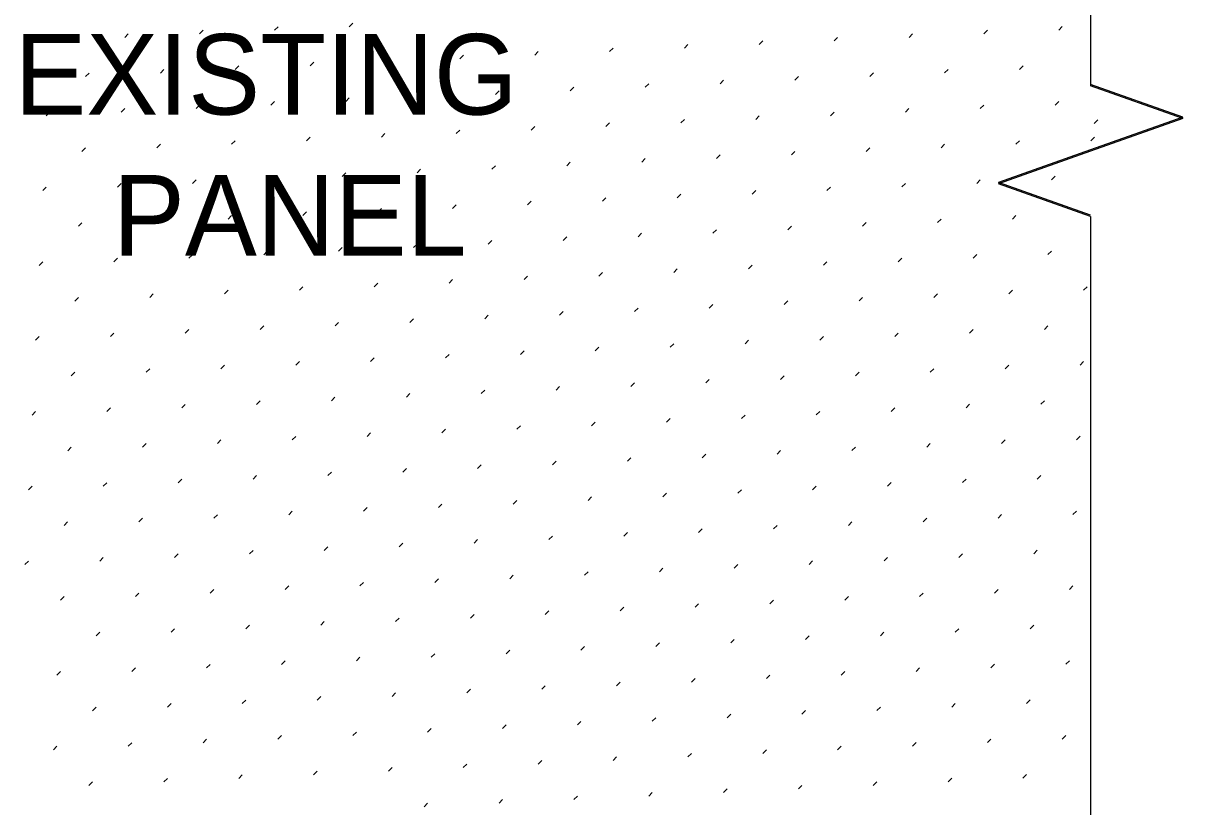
# Model space of a CAD drawing. Extents: x 49991.4 to 50021, y 49987.6 to 50011.4.
# Drawn here: x 50014.071 to 50015.222, y 49994.884 to 49995.662 of the extents above; entities that cross this region are included whole.
import ezdxf

# ---------------------------------------------------------------- set-up
doc = ezdxf.new("R2010")
doc.units = 0
for name, color, linetype in [('Level 10', 7, 'Continuous'), ('Level 2', 7, 'Continuous'), ('Level 6', 7, 'Continuous')]:
    doc.layers.add(name, color=color, linetype=linetype)

msp = doc.modelspace()

# ---------------------------------------------------------------- linework, layer by layer
at = {"layer": 'Level 10'}
for p, q in [((50014.3948, 49995.6587), (50014.3984, 49995.6623)), ((50014.1721, 49995.6481), (50014.1756, 49995.6516)), ((50014.2463, 49995.6516), (50014.2499, 49995.6552)), ((50014.3206, 49995.6552), (50014.3241, 49995.6587)), ((50014.95, 49995.6482), (50014.9535, 49995.6517)), ((50015.0242, 49995.6517), (50015.0277, 49995.6552)), ((50015.0985, 49995.6552), (50015.102, 49995.6588)), ((50014.0978, 49995.6445), (50014.1013, 49995.6481)), ((50014.7272, 49995.6375), (50014.7307, 49995.6411)), ((50014.8014, 49995.6411), (50014.805, 49995.6446)), ((50014.8757, 49995.6446), (50014.8792, 49995.6482)), ((50014.5044, 49995.6269), (50014.508, 49995.6304)), ((50014.5787, 49995.6304), (50014.5822, 49995.634)), ((50014.6529, 49995.634), (50014.6565, 49995.6375)), ((50014.2074, 49995.6127), (50014.211, 49995.6163)), ((50014.2817, 49995.6163), (50014.2852, 49995.6198)), ((50014.3559, 49995.6198), (50014.3595, 49995.6234)), ((50014.4302, 49995.6234), (50014.4337, 49995.6269)), ((50014.9853, 49995.6128), (50014.9888, 49995.6163)), ((50015.0596, 49995.6163), (50015.0631, 49995.6199)), ((50014.1332, 49995.6092), (50014.1367, 49995.6127)), ((50014.7625, 49995.6022), (50014.7661, 49995.6057)), ((50014.8368, 49995.6057), (50014.8403, 49995.6093)), ((50014.9111, 49995.6093), (50014.9146, 49995.6128)), ((50014.5398, 49995.5916), (50014.5433, 49995.5951)), ((50014.614, 49995.5951), (50014.6176, 49995.5986)), ((50014.6883, 49995.5986), (50014.6918, 49995.6022)), ((50014.317, 49995.5809), (50014.3206, 49995.5845)), ((50014.3913, 49995.5845), (50014.3948, 49995.588)), ((50014.4655, 49995.588), (50014.4691, 49995.5915)), ((50015.0949, 49995.581), (50015.0985, 49995.5845)), ((50014.0943, 49995.5703), (50014.0978, 49995.5738)), ((50014.1685, 49995.5738), (50014.1721, 49995.5774)), ((50014.2428, 49995.5774), (50014.2463, 49995.5809)), ((50014.7979, 49995.5668), (50014.8014, 49995.5704)), ((50014.8722, 49995.5704), (50014.8757, 49995.5739)), ((50014.9464, 49995.5739), (50014.9499, 49995.5774)), ((50015.0207, 49995.5775), (50015.0242, 49995.581)), ((50014.5751, 49995.5562), (50014.5787, 49995.5597)), ((50014.6494, 49995.5597), (50014.6529, 49995.5633)), ((50014.7236, 49995.5633), (50014.7272, 49995.5668)), ((50015.1337, 49995.5628), (50015.1372, 49995.5664)), ((50014.3524, 49995.5456), (50014.3559, 49995.5491)), ((50014.4266, 49995.5491), (50014.4302, 49995.5526)), ((50014.5009, 49995.5527), (50014.5044, 49995.5562)), ((50015.1303, 49995.5456), (50015.1338, 49995.5492)), ((50014.1296, 49995.5349), (50014.1332, 49995.5385)), ((50014.2039, 49995.5385), (50014.2074, 49995.542)), ((50014.2781, 49995.542), (50014.2817, 49995.5456)), ((50014.9075, 49995.535), (50014.911, 49995.5385)), ((50014.9818, 49995.5386), (50014.9853, 49995.5421)), ((50015.056, 49995.5421), (50015.0596, 49995.5456)), ((50014.6105, 49995.5208), (50014.614, 49995.5244)), ((50014.6848, 49995.5244), (50014.6883, 49995.5279)), ((50014.759, 49995.5279), (50014.7625, 49995.5315)), ((50014.8333, 49995.5315), (50014.8368, 49995.535)), ((50014.3877, 49995.5102), (50014.3913, 49995.5137)), ((50014.462, 49995.5138), (50014.4655, 49995.5173)), ((50014.5362, 49995.5173), (50014.5398, 49995.5208)), ((50014.165, 49995.4996), (50014.1685, 49995.5031)), ((50014.2392, 49995.5031), (50014.2428, 49995.5067)), ((50014.3135, 49995.5067), (50014.317, 49995.5102)), ((50014.9429, 49995.4997), (50014.9464, 49995.5032)), ((50015.0171, 49995.5032), (50015.0207, 49995.5067)), ((50015.0914, 49995.5067), (50015.0949, 49995.5103)), ((50014.0907, 49995.496), (50014.0943, 49995.4996)), ((50014.7201, 49995.489), (50014.7236, 49995.4926)), ((50014.7944, 49995.4926), (50014.7979, 49995.4961)), ((50014.8686, 49995.4961), (50014.8721, 49995.4996)), ((50014.4231, 49995.4749), (50014.4266, 49995.4784)), ((50014.4973, 49995.4784), (50014.5009, 49995.4819)), ((50014.5716, 49995.4819), (50014.5751, 49995.4855)), ((50014.6459, 49995.4855), (50014.6494, 49995.489)), ((50014.2003, 49995.4642), (50014.2039, 49995.4678)), ((50014.2746, 49995.4678), (50014.2781, 49995.4713)), ((50014.3488, 49995.4713), (50014.3524, 49995.4749)), ((50014.9782, 49995.4643), (50014.9818, 49995.4678)), ((50015.0525, 49995.4678), (50015.056, 49995.4714)), ((50014.1261, 49995.4607), (50014.1296, 49995.4642)), ((50014.7555, 49995.4537), (50014.759, 49995.4572)), ((50014.8297, 49995.4572), (50014.8333, 49995.4608)), ((50014.904, 49995.4608), (50014.9075, 49995.4643)), ((50014.5327, 49995.443), (50014.5362, 49995.4466)), ((50014.607, 49995.4466), (50014.6105, 49995.4501)), ((50014.6812, 49995.4501), (50014.6847, 49995.4537)), ((50014.2357, 49995.4289), (50014.2392, 49995.4324)), ((50014.3099, 49995.4324), (50014.3135, 49995.436)), ((50014.3842, 49995.436), (50014.3877, 49995.4395)), ((50014.4584, 49995.4395), (50014.462, 49995.443)), ((50015.0136, 49995.4289), (50015.0171, 49995.4325)), ((50015.0878, 49995.4325), (50015.0914, 49995.436)), ((50014.0872, 49995.4218), (50014.0907, 49995.4253)), ((50014.1614, 49995.4253), (50014.165, 49995.4289)), ((50014.7908, 49995.4183), (50014.7944, 49995.4219)), ((50014.8651, 49995.4219), (50014.8686, 49995.4254)), ((50014.9393, 49995.4254), (50014.9429, 49995.4289)), ((50014.5681, 49995.4077), (50014.5716, 49995.4112)), ((50014.6423, 49995.4112), (50014.6458, 49995.4148)), ((50014.7166, 49995.4148), (50014.7201, 49995.4183)), ((50014.3453, 49995.3971), (50014.3488, 49995.4006)), ((50014.4196, 49995.4006), (50014.4231, 49995.4041)), ((50014.4938, 49995.4041), (50014.4973, 49995.4077)), ((50015.1232, 49995.3971), (50015.1267, 49995.4007)), ((50014.1225, 49995.3864), (50014.1261, 49995.39)), ((50014.1968, 49995.39), (50014.2003, 49995.3935)), ((50014.271, 49995.3935), (50014.2746, 49995.3971)), ((50014.8262, 49995.383), (50014.8297, 49995.3865)), ((50014.9004, 49995.3865), (50014.904, 49995.39)), ((50014.9747, 49995.39), (50014.9782, 49995.3936)), ((50015.0489, 49995.3936), (50015.0525, 49995.3971)), ((50014.6034, 49995.3723), (50014.6069, 49995.3759)), ((50014.6777, 49995.3759), (50014.6812, 49995.3794)), ((50014.7519, 49995.3794), (50014.7555, 49995.383)), ((50014.3807, 49995.3617), (50014.3842, 49995.3652)), ((50014.4549, 49995.3652), (50014.4584, 49995.3688)), ((50014.5292, 49995.3688), (50014.5327, 49995.3723)), ((50014.1579, 49995.3511), (50014.1614, 49995.3546)), ((50014.2321, 49995.3546), (50014.2357, 49995.3582)), ((50014.3064, 49995.3582), (50014.3099, 49995.3617)), ((50014.9358, 49995.3511), (50014.9393, 49995.3547)), ((50015.01, 49995.3547), (50015.0136, 49995.3582)), ((50015.0843, 49995.3582), (50015.0878, 49995.3618)), ((50014.0836, 49995.3475), (50014.0872, 49995.3511)), ((50014.6388, 49995.337), (50014.6423, 49995.3405)), ((50014.713, 49995.3405), (50014.7166, 49995.3441)), ((50014.7873, 49995.3441), (50014.7908, 49995.3476)), ((50014.8615, 49995.3476), (50014.8651, 49995.3511)), ((50014.416, 49995.3264), (50014.4195, 49995.3299)), ((50014.4903, 49995.3299), (50014.4938, 49995.3334)), ((50014.5645, 49995.3334), (50014.5681, 49995.337)), ((50014.1932, 49995.3157), (50014.1968, 49995.3193)), ((50014.2675, 49995.3193), (50014.271, 49995.3228)), ((50014.3418, 49995.3228), (50014.3453, 49995.3263)), ((50014.9711, 49995.3158), (50014.9747, 49995.3193)), ((50015.0454, 49995.3193), (50015.0489, 49995.3229)), ((50015.1196, 49995.3229), (50015.1232, 49995.3264)), ((50014.119, 49995.3122), (50014.1225, 49995.3157)), ((50014.7484, 49995.3052), (50014.7519, 49995.3087)), ((50014.8226, 49995.3087), (50014.8262, 49995.3122)), ((50014.8969, 49995.3123), (50014.9004, 49995.3158)), ((50014.4514, 49995.291), (50014.4549, 49995.2945)), ((50014.5256, 49995.2945), (50014.5292, 49995.2981)), ((50014.5999, 49995.2981), (50014.6034, 49995.3016)), ((50014.6741, 49995.3016), (50014.6777, 49995.3052)), ((50014.2286, 49995.2804), (50014.2321, 49995.2839)), ((50014.3029, 49995.2839), (50014.3064, 49995.2874)), ((50014.3771, 49995.2875), (50014.3806, 49995.291)), ((50015.0065, 49995.2804), (50015.01, 49995.284)), ((50015.0807, 49995.284), (50015.0843, 49995.2875)), ((50014.0801, 49995.2733), (50014.0836, 49995.2768)), ((50014.1544, 49995.2768), (50014.1579, 49995.2804)), ((50014.7837, 49995.2698), (50014.7873, 49995.2733)), ((50014.858, 49995.2734), (50014.8615, 49995.2769)), ((50014.9322, 49995.2769), (50014.9358, 49995.2804)), ((50014.561, 49995.2592), (50014.5645, 49995.2627)), ((50014.6352, 49995.2627), (50014.6388, 49995.2663)), ((50014.7095, 49995.2663), (50014.713, 49995.2698)), ((50014.264, 49995.245), (50014.2675, 49995.2485)), ((50014.3382, 49995.2486), (50014.3417, 49995.2521)), ((50014.4125, 49995.2521), (50014.416, 49995.2556)), ((50014.4867, 49995.2556), (50014.4903, 49995.2592)), ((50015.0418, 49995.2451), (50015.0454, 49995.2486)), ((50015.1161, 49995.2486), (50015.1196, 49995.2522)), ((50014.1155, 49995.2379), (50014.119, 49995.2415)), ((50014.1897, 49995.2415), (50014.1932, 49995.245)), ((50014.8191, 49995.2345), (50014.8226, 49995.238)), ((50014.8933, 49995.238), (50014.8969, 49995.2415)), ((50014.9676, 49995.2415), (50014.9711, 49995.2451)), ((50014.5963, 49995.2238), (50014.5999, 49995.2274)), ((50014.6706, 49995.2274), (50014.6741, 49995.2309)), ((50014.7448, 49995.2309), (50014.7484, 49995.2344)), ((50014.3736, 49995.2132), (50014.3771, 49995.2167)), ((50014.4478, 49995.2167), (50014.4514, 49995.2203)), ((50014.5221, 49995.2203), (50014.5256, 49995.2238)), ((50014.0766, 49995.199), (50014.0801, 49995.2026)), ((50014.1508, 49995.2026), (50014.1543, 49995.2061)), ((50014.2251, 49995.2061), (50014.2286, 49995.2097)), ((50014.2993, 49995.2097), (50014.3028, 49995.2132)), ((50014.8544, 49995.1991), (50014.858, 49995.2026)), ((50014.9287, 49995.2026), (50014.9322, 49995.2062)), ((50015.0029, 49995.2062), (50015.0065, 49995.2097)), ((50015.0772, 49995.2097), (50015.0807, 49995.2133)), ((50014.6317, 49995.1885), (50014.6352, 49995.192)), ((50014.7059, 49995.192), (50014.7095, 49995.1956)), ((50014.7802, 49995.1956), (50014.7837, 49995.1991)), ((50014.4089, 49995.1778), (50014.4125, 49995.1814)), ((50014.4832, 49995.1814), (50014.4867, 49995.1849)), ((50014.5574, 49995.1849), (50014.561, 49995.1885)), ((50014.1862, 49995.1672), (50014.1897, 49995.1708)), ((50014.2604, 49995.1708), (50014.264, 49995.1743)), ((50014.3347, 49995.1743), (50014.3382, 49995.1778)), ((50014.9641, 49995.1673), (50014.9676, 49995.1708)), ((50015.0383, 49995.1708), (50015.0418, 49995.1744)), ((50015.1126, 49995.1744), (50015.1161, 49995.1779)), ((50014.1119, 49995.1637), (50014.1154, 49995.1672)), ((50014.667, 49995.1531), (50014.6706, 49995.1567)), ((50014.7413, 49995.1567), (50014.7448, 49995.1602)), ((50014.8155, 49995.1602), (50014.8191, 49995.1637)), ((50014.8898, 49995.1637), (50014.8933, 49995.1673)), ((50014.4443, 49995.1425), (50014.4478, 49995.146)), ((50014.5185, 49995.146), (50014.5221, 49995.1496)), ((50014.5928, 49995.1496), (50014.5963, 49995.1531)), ((50014.2215, 49995.1319), (50014.2251, 49995.1354)), ((50014.2958, 49995.1354), (50014.2993, 49995.1389)), ((50014.37, 49995.1389), (50014.3736, 49995.1425)), ((50014.9994, 49995.1319), (50015.0029, 49995.1355)), ((50015.0737, 49995.1355), (50015.0772, 49995.139)), ((50014.073, 49995.1248), (50014.0765, 49995.1283)), ((50014.1473, 49995.1283), (50014.1508, 49995.1319)), ((50014.7766, 49995.1213), (50014.7802, 49995.1248)), ((50014.8509, 49995.1248), (50014.8544, 49995.1284)), ((50014.9252, 49995.1284), (50014.9287, 49995.1319)), ((50014.4796, 49995.1071), (50014.4832, 49995.1107)), ((50014.5539, 49995.1107), (50014.5574, 49995.1142)), ((50014.6281, 49995.1142), (50014.6317, 49995.1178)), ((50014.7024, 49995.1178), (50014.7059, 49995.1213)), ((50014.2569, 49995.0965), (50014.2604, 49995.1)), ((50014.3311, 49995.1), (50014.3347, 49995.1036)), ((50014.4054, 49995.1036), (50014.4089, 49995.1071)), ((50015.0348, 49995.0966), (50015.0383, 49995.1001)), ((50015.109, 49995.1001), (50015.1126, 49995.1037)), ((50014.1084, 49995.0894), (50014.1119, 49995.093)), ((50014.1826, 49995.093), (50014.1862, 49995.0965)), ((50014.812, 49995.0859), (50014.8155, 49995.0895)), ((50014.8863, 49995.0895), (50014.8898, 49995.093)), ((50014.9605, 49995.093), (50014.964, 49995.0966)), ((50014.5892, 49995.0753), (50014.5928, 49995.0789)), ((50014.6635, 49995.0789), (50014.667, 49995.0824)), ((50014.7377, 49995.0824), (50014.7413, 49995.0859)), ((50014.2922, 49995.0612), (50014.2958, 49995.0647)), ((50014.3665, 49995.0647), (50014.37, 49995.0682)), ((50014.4407, 49995.0682), (50014.4443, 49995.0718)), ((50014.515, 49995.0718), (50014.5185, 49995.0753)), ((50015.0701, 49995.0612), (50015.0737, 49995.0648)), ((50014.1437, 49995.0541), (50014.1473, 49995.0576)), ((50014.218, 49995.0576), (50014.2215, 49995.0611)), ((50014.8474, 49995.0506), (50014.8509, 49995.0541)), ((50014.9216, 49995.0541), (50014.9251, 49995.0577)), ((50014.9959, 49995.0577), (50014.9994, 49995.0612)), ((50014.6246, 49995.04), (50014.6281, 49995.0435)), ((50014.6989, 49995.0435), (50014.7024, 49995.047)), ((50014.7731, 49995.0471), (50014.7766, 49995.0506)), ((50014.4018, 49995.0293), (50014.4054, 49995.0329)), ((50014.4761, 49995.0329), (50014.4796, 49995.0364)), ((50014.5503, 49995.0364), (50014.5539, 49995.04)), ((50014.1048, 49995.0152), (50014.1084, 49995.0187)), ((50014.1791, 49995.0187), (50014.1826, 49995.0222)), ((50014.2533, 49995.0223), (50014.2569, 49995.0258)), ((50014.3276, 49995.0258), (50014.3311, 49995.0293)), ((50014.8827, 49995.0152), (50014.8862, 49995.0188)), ((50014.957, 49995.0188), (50014.9605, 49995.0223)), ((50015.0312, 49995.0223), (50015.0348, 49995.0259)), ((50015.1055, 49995.0259), (50015.109, 49995.0294)), ((50014.66, 49995.0046), (50014.6635, 49995.0081)), ((50014.7342, 49995.0082), (50014.7377, 49995.0117)), ((50014.8085, 49995.0117), (50014.812, 49995.0152)), ((50014.4372, 49994.994), (50014.4407, 49994.9975)), ((50014.5114, 49994.9975), (50014.515, 49995.0011)), ((50014.5857, 49995.0011), (50014.5892, 49995.0046)), ((50014.2144, 49994.9834), (50014.218, 49994.9869)), ((50014.2887, 49994.9869), (50014.2922, 49994.9904)), ((50014.3629, 49994.9904), (50014.3665, 49994.994)), ((50014.9923, 49994.9834), (50014.9959, 49994.987)), ((50015.0666, 49994.987), (50015.0701, 49994.9905)), ((50014.1402, 49994.9798), (50014.1437, 49994.9833)), ((50014.6953, 49994.9693), (50014.6988, 49994.9728)), ((50014.7696, 49994.9728), (50014.7731, 49994.9763)), ((50014.8438, 49994.9763), (50014.8474, 49994.9799)), ((50014.9181, 49994.9799), (50014.9216, 49994.9834)), ((50014.4725, 49994.9586), (50014.4761, 49994.9622)), ((50014.5468, 49994.9622), (50014.5503, 49994.9657)), ((50014.6211, 49994.9657), (50014.6246, 49994.9692)), ((50014.2498, 49994.948), (50014.2533, 49994.9515)), ((50014.324, 49994.9515), (50014.3276, 49994.9551)), ((50014.3983, 49994.9551), (50014.4018, 49994.9586)), ((50015.0277, 49994.9481), (50015.0312, 49994.9516)), ((50015.1019, 49994.9516), (50015.1055, 49994.9551)), ((50014.1013, 49994.9409), (50014.1048, 49994.9445)), ((50014.1755, 49994.9445), (50014.1791, 49994.948)), ((50014.8049, 49994.9374), (50014.8085, 49994.941)), ((50014.8792, 49994.941), (50014.8827, 49994.9445)), ((50014.9534, 49994.9445), (50014.957, 49994.9481)), ((50014.5079, 49994.9233), (50014.5114, 49994.9268)), ((50014.5822, 49994.9268), (50014.5857, 49994.9304)), ((50014.6564, 49994.9304), (50014.6599, 49994.9339)), ((50014.7307, 49994.9339), (50014.7342, 49994.9374)), ((50014.2851, 49994.9126), (50014.2887, 49994.9162)), ((50014.3594, 49994.9162), (50014.3629, 49994.9197)), ((50014.4337, 49994.9197), (50014.4372, 49994.9233)), ((50015.063, 49994.9127), (50015.0666, 49994.9163)), ((50014.1366, 49994.9056), (50014.1402, 49994.9091)), ((50014.2109, 49994.9091), (50014.2144, 49994.9126)), ((50014.8403, 49994.9021), (50014.8438, 49994.9056)), ((50014.9145, 49994.9056), (50014.9181, 49994.9092)), ((50014.9888, 49994.9092), (50014.9923, 49994.9127)), ((50014.6175, 49994.8915), (50014.621, 49994.895)), ((50014.6918, 49994.895), (50014.6953, 49994.8985)), ((50014.766, 49994.8985), (50014.7696, 49994.9021)), ((50014.469, 49994.8844), (50014.4725, 49994.8879)), ((50014.5433, 49994.8879), (50014.5468, 49994.8915))]:
    msp.add_line(p, q, dxfattribs=at)
at = {"layer": 'Level 6'}
for p, q in [((50015.1301, 49996.9704), (50015.1301, 49995.6)), ((50015.2215, 49995.5689), (50015.1301, 49995.6013)), ((50015.2215, 49995.5676), (50015.1301, 49995.6)), ((50015.2215, 49995.5689), (50015.1301, 49995.5365)), ((50015.2215, 49995.5676), (50015.1301, 49995.5352)), ((50015.1301, 49995.5365), (50015.0387, 49995.5041)), ((50015.1301, 49995.5352), (50015.0387, 49995.5028)), ((50015.1301, 49995.4717), (50015.0387, 49995.5041)), ((50015.1301, 49995.4704), (50015.0387, 49995.5028)), ((50015.1301, 49995.4704), (50015.1301, 49994.1903))]:
    msp.add_line(p, q, dxfattribs=at)

# ---------------------------------------------------------------- texts
at = {"layer": 'Level 2'}
for s, p in [('EXISTING', (50014.0626, 49995.5715)), ('PANEL', (50014.1604, 49995.4315))]:
    msp.add_text(s, height=0.08, dxfattribs=at).set_placement(p)

doc.saveas('drawing.dxf')
